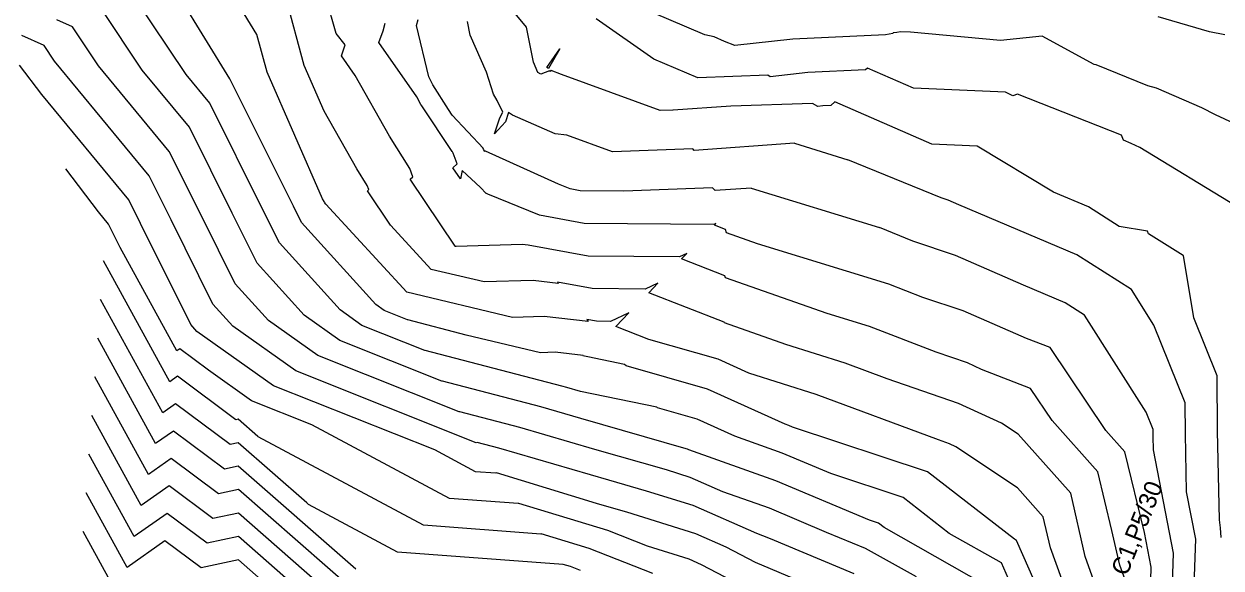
# Model space of a CAD drawing. Extents: x -549394 to -546608, y -1037055 to -1033629.
# Drawn here: x -548465 to -547751, y -1035300 to -1034976 of the extents above; entities that cross this region are included whole.
import ezdxf

# ---------------------------------------------------------------- set-up
doc = ezdxf.new("R2010")
doc.units = 0
for name, color, linetype in [('hlavni_vrst', 7, 'Continuous'), ('norm_vrst', 7, 'Continuous'), ('x_popis_velky_C1', 7, 'Continuous')]:
    doc.layers.add(name, color=color, linetype=linetype)

msp = doc.modelspace()

# ---------------------------------------------------------------- linework, layer by layer
at = {"layer": 'hlavni_vrst'}
for p, q in [((-548325.66, -1034981.81), (-548350.92, -1034940.67)), ((-548198.58, -1034982.16), (-548200.15, -1034974.14)), ((-548452.63, -1034988.35), (-548465.78, -1034982.48)), ((-548319.63, -1035004.27), (-548325.66, -1034981.81)), ((-548188.85, -1035004.3), (-548198.58, -1034982.16)), ((-548446.34, -1034997.78), (-548452.63, -1034988.35)), ((-548390, -1035066.03), (-548446.34, -1034997.78)), ((-548286.55, -1035079.75), (-548319.63, -1035004.27)), ((-548184.56, -1035017.32), (-548188.85, -1035004.3)), ((-548182.4, -1035021.26), (-548184.56, -1035017.32)), ((-548179.09, -1035028.24), (-548182.4, -1035021.26)), ((-548180.87, -1035031.46), (-548179.09, -1035028.24)), ((-548175.69, -1035028.31), (-548177.55, -1035033.94)), ((-548173.24, -1035030), (-548175.69, -1035028.31)), ((-548147.84, -1035041.1), (-548173.24, -1035030)), ((-548184.04, -1035041.05), (-548180.87, -1035031.46)), ((-548177.55, -1035033.94), (-548184.04, -1035041.05)), ((-548140.91, -1035041.86), (-548147.84, -1035041.1)), ((-548113.62, -1035051.86), (-548140.91, -1035041.86)), ((-548065.86, -1035050.08), (-548113.62, -1035051.86)), ((-548065.01, -1035050.95), (-548065.86, -1035050.08)), ((-548005.07, -1035046.73), (-548065.01, -1035050.95)), ((-548005.07, -1035046.73), (-547973.33, -1035056.54)), ((-547917.64, -1035079.24), (-547973.33, -1035056.54)), ((-548376.85, -1035092.43), (-548390, -1035066.03)), ((-548285.63, -1035081.39), (-548286.55, -1035079.75)), ((-547913.58, -1035080.58), (-547917.64, -1035079.24)), ((-547907.13, -1035083.41), (-547913.58, -1035080.58)), ((-548285.33, -1035081.86), (-548285.63, -1035081.39)), ((-548285.28, -1035081.98), (-548285.33, -1035081.86)), ((-548285.32, -1035082.01), (-548285.28, -1035081.98)), ((-548284.67, -1035082.98), (-548285.32, -1035082.01)), ((-548236.21, -1035135.54), (-548284.67, -1035082.98)), ((-547836.8, -1035113.3), (-547907.13, -1035083.41)), ((-548351.89, -1035142.66), (-548376.85, -1035092.43)), ((-547804.28, -1035133.96), (-547836.8, -1035113.3)), ((-548173.36, -1035150.54), (-548236.21, -1035135.54)), ((-547790.8, -1035155.21), (-547804.28, -1035133.96)), ((-548340.1, -1035155.69), (-548351.89, -1035142.66)), ((-548154.35, -1035149.97), (-548173.36, -1035150.54)), ((-548128.27, -1035153.07), (-548154.35, -1035149.97)), ((-548128.87, -1035151.85), (-548128.27, -1035153.07)), ((-548123.28, -1035152.88), (-548128.87, -1035151.85)), ((-548103.97, -1035147.78), (-548114.78, -1035152.95)), ((-548111.62, -1035156.06), (-548103.97, -1035147.78)), ((-548302.57, -1035182.36), (-548340.1, -1035155.69)), ((-548114.78, -1035152.95), (-548123.28, -1035152.88)), ((-548092.08, -1035163.7), (-548111.62, -1035156.06)), ((-547772.19, -1035201.51), (-547790.8, -1035155.21)), ((-548386.12, -1035225.87), (-548420.65, -1035162.96)), ((-548050.71, -1035175.57), (-548092.08, -1035163.7)), ((-548032.28, -1035183.89), (-548050.71, -1035175.57)), ((-548194.87, -1035225.3), (-548302.57, -1035182.36)), ((-547992.26, -1035196.59), (-548032.28, -1035183.89)), ((-547919.24, -1035223.68), (-547992.26, -1035196.59)), ((-547772.07, -1035219.94), (-547772.19, -1035201.51)), ((-548375.5, -1035218.38), (-548386.12, -1035225.87)), ((-548345.09, -1035241.08), (-548375.5, -1035218.38)), ((-547912.76, -1035225.91), (-547919.24, -1035223.68)), ((-547771.32, -1035254.67), (-547772.07, -1035219.94)), ((-548194.43, -1035225.12), (-548194.87, -1035225.3)), ((-548181.41, -1035228.51), (-548194.43, -1035225.12)), ((-548115.8, -1035247.72), (-548181.41, -1035228.51)), ((-547908.84, -1035227.71), (-547912.76, -1035225.91)), ((-547872.12, -1035252.29), (-547908.84, -1035227.71)), ((-548336.78, -1035239.3), (-548345.09, -1035241.08)), ((-548266.71, -1035300.68), (-548336.78, -1035239.3)), ((-548093.34, -1035254.17), (-548115.8, -1035247.72)), ((-547856.77, -1035269.47), (-547872.12, -1035252.29)), ((-548065.61, -1035262.83), (-548093.34, -1035254.17)), ((-547765.9, -1035282.86), (-547771.32, -1035254.67)), ((-548027.59, -1035279.53), (-548065.61, -1035262.83)), ((-547852.53, -1035288.02), (-547856.77, -1035269.47)), ((-548407.38, -1035318.19), (-548429.29, -1035278.27)), ((-548023.97, -1035280.82), (-548027.59, -1035279.53)), ((-548019.52, -1035282.69), (-548023.97, -1035280.82)), ((-547969.61, -1035303.43), (-548019.52, -1035282.69)), ((-547838.26, -1035327.5), (-547852.53, -1035288.02)), ((-547767.77, -1035343.03), (-547765.9, -1035282.86))]:
    msp.add_line(p, q, dxfattribs=at)
at = {"layer": 'norm_vrst'}
for p, q in [((-548278.35, -1034981.13), (-548292.99, -1034930.32)), ((-548341.75, -1035008.31), (-548379.76, -1034946.38)), ((-548164.85, -1034977.44), (-548190.85, -1034946.02)), ((-548367.9, -1035005.68), (-548401.52, -1034955.28)), ((-548297.51, -1035000.24), (-548309.57, -1034955.32)), ((-548394.04, -1035003.04), (-548418.56, -1034966.31)), ((-548058.63, -1034981.96), (-548100.16, -1034964.38)), ((-548435.59, -1034977.33), (-548445.09, -1034973.09)), ((-548230.55, -1034976.55), (-548229.52, -1034972.92)), ((-548088.99, -1034996.46), (-548123.33, -1034972.47)), ((-547757.67, -1034980.24), (-547788.2, -1034971.26)), ((-548420.19, -1035000.41), (-548435.59, -1034977.33)), ((-548272.98, -1034987.99), (-548278.35, -1034981.13)), ((-548252.94, -1034986.52), (-548250.47, -1034979.54)), ((-548250.47, -1034979.54), (-548249.2, -1034975.11)), ((-548223.12, -1035007.15), (-548230.55, -1034976.55)), ((-548160.75, -1034998.41), (-548164.85, -1034977.44)), ((-547946.54, -1034981.28), (-547946.3, -1034980.79)), ((-547944.08, -1034980.7), (-547946.3, -1034980.79)), ((-547941.91, -1034980.32), (-547944.08, -1034980.7)), ((-547935.98, -1034980.42), (-547941.91, -1034980.32)), ((-547882.24, -1034985.31), (-547935.98, -1034980.42)), ((-547748.61, -1034981.97), (-547757.67, -1034980.24)), ((-548275.29, -1034994.5), (-548272.98, -1034987.99)), ((-548230.34, -1035018.92), (-548252.94, -1034986.52)), ((-548052.96, -1034983.31), (-548058.63, -1034981.96)), ((-548046.88, -1034986.05), (-548052.96, -1034983.31)), ((-548040.77, -1034988.45), (-548046.88, -1034986.05)), ((-548006.16, -1034984.53), (-548040.77, -1034988.45)), ((-547950.83, -1034982.06), (-548006.16, -1034984.53)), ((-547946.54, -1034981.28), (-547950.83, -1034982.06)), ((-547857.36, -1034982.81), (-547882.24, -1034985.31)), ((-547857.36, -1034982.81), (-547857.36, -1034982.81)), ((-547857.36, -1034982.81), (-547857.36, -1034982.81)), ((-547826.38, -1034999.75), (-547857.36, -1034982.81)), ((-547857.36, -1034982.81), (-547857.36, -1034982.81)), ((-548267.08, -1035006.27), (-548275.29, -1034994.5)), ((-548152.72, -1035001.43), (-548144.97, -1034990.32)), ((-548144.97, -1034990.32), (-548151.83, -1035002.04)), ((-548453.9, -1035017.66), (-548467.28, -1035000.09)), ((-548377.94, -1035051.6), (-548420.19, -1035000.41)), ((-548285.5, -1035027.64), (-548297.51, -1035000.24)), ((-548158.12, -1035004.39), (-548160.75, -1034998.41)), ((-548151.83, -1035002.04), (-548152.72, -1035001.43)), ((-548062.77, -1035007.57), (-548088.99, -1034996.46)), ((-547961.61, -1035001.88), (-547962.72, -1035002.96)), ((-547934.25, -1035013.86), (-547961.61, -1035001.88)), ((-547825.25, -1034999.86), (-547826.38, -1034999.75)), ((-547794.43, -1035012.39), (-547825.25, -1034999.86)), ((-548365.87, -1035037.17), (-548394.04, -1035003.04)), ((-548353.81, -1035022.74), (-548367.9, -1035005.68)), ((-548341.75, -1035008.31), (-548341.75, -1035008.31)), ((-548303.92, -1035084.29), (-548341.75, -1035008.31)), ((-548341.75, -1035008.31), (-548341.75, -1035008.31)), ((-548341.75, -1035008.31), (-548341.75, -1035008.31)), ((-548341.75, -1035008.31), (-548341.75, -1035008.31)), ((-548246.66, -1035042.42), (-548267.08, -1035006.27)), ((-548220.78, -1035011.77), (-548223.12, -1035007.15)), ((-548156.32, -1035005.56), (-548158.12, -1035004.39)), ((-548151.28, -1035003.53), (-548156.32, -1035005.56)), ((-548150.87, -1035003.8), (-548151.28, -1035003.53)), ((-548150.53, -1035003.22), (-548150.87, -1035003.8)), ((-548150.23, -1035003.21), (-548150.53, -1035003.22)), ((-548144.1, -1035005.61), (-548150.23, -1035003.21)), ((-548085.32, -1035027.15), (-548144.1, -1035005.61)), ((-548021.12, -1035006.17), (-548062.77, -1035007.57)), ((-548019.64, -1035007.04), (-548021.12, -1035006.17)), ((-547997.16, -1035004.49), (-548019.64, -1035007.04)), ((-547962.72, -1035002.96), (-547997.16, -1035004.49)), ((-548211.54, -1035026.58), (-548220.78, -1035011.77)), ((-547879.35, -1035016.27), (-547934.25, -1035013.86)), ((-547875.02, -1035018.31), (-547879.35, -1035016.27)), ((-547789.31, -1035013.76), (-547794.43, -1035012.39)), ((-547762.3, -1035025.65), (-547789.31, -1035013.76)), ((-548402.06, -1035080.46), (-548453.9, -1035017.66)), ((-548322.15, -1035086.33), (-548353.81, -1035022.74)), ((-548228.03, -1035023.48), (-548230.34, -1035018.92)), ((-548227.43, -1035024.45), (-548228.03, -1035023.48)), ((-547994.44, -1035022.94), (-548043.03, -1035024.57)), ((-547991.25, -1035024.81), (-547994.44, -1035022.94)), ((-547981.06, -1035021.97), (-547983.4, -1035024.24)), ((-547923.31, -1035047.26), (-547981.06, -1035021.97)), ((-547872.2, -1035017.4), (-547875.02, -1035018.31)), ((-547810.24, -1035041.96), (-547872.2, -1035017.4)), ((-548266.14, -1035061.9), (-548285.5, -1035027.64)), ((-548209.24, -1035051.53), (-548227.43, -1035024.45)), ((-548209.31, -1035029.91), (-548211.54, -1035026.58)), ((-548190.65, -1035049.83), (-548209.31, -1035029.91)), ((-548077.69, -1035026.86), (-548085.32, -1035027.15)), ((-548077.56, -1035027), (-548077.69, -1035026.86)), ((-548043.03, -1035024.57), (-548077.56, -1035027)), ((-547988.15, -1035024.46), (-547991.25, -1035024.81)), ((-547983.4, -1035024.24), (-547988.15, -1035024.46)), ((-547754.19, -1035029.66), (-547762.3, -1035025.65)), ((-547730.63, -1035040.65), (-547754.19, -1035029.66)), ((-548340.39, -1035088.36), (-548365.87, -1035037.17)), ((-548234.43, -1035061.72), (-548246.66, -1035042.42)), ((-547809.05, -1035044.85), (-547810.24, -1035041.96)), ((-547804.46, -1035046.79), (-547809.05, -1035044.85)), ((-548358.62, -1035090.4), (-548377.94, -1035051.6)), ((-548209.06, -1035051.73), (-548209.24, -1035051.53)), ((-548208.83, -1035052.15), (-548209.06, -1035051.73)), ((-548209.06, -1035051.73), (-548209.06, -1035051.73)), ((-548208.64, -1035052.6), (-548208.83, -1035052.15)), ((-548190.85, -1035049.89), (-548190.65, -1035049.83)), ((-548190.6, -1035050.34), (-548190.85, -1035049.89)), ((-548190.33, -1035050.52), (-548190.6, -1035050.34)), ((-548189.76, -1035051.65), (-548190.33, -1035050.52)), ((-548189.69, -1035051.4), (-548189.76, -1035051.65)), ((-548189.33, -1035051.47), (-548189.69, -1035051.4)), ((-548145.92, -1035071.14), (-548189.33, -1035051.47)), ((-547896.2, -1035048.45), (-547923.31, -1035047.26)), ((-547850.71, -1035075.86), (-547896.2, -1035048.45)), ((-547799.24, -1035049.25), (-547804.46, -1035046.79)), ((-547741.82, -1035084.17), (-547799.24, -1035049.25)), ((-548208.8, -1035061.28), (-548206.31, -1035059.06)), ((-548206.31, -1035059.06), (-548208.64, -1035052.6)), ((-548420.09, -1035087.67), (-548439.72, -1035061.88)), ((-548259.88, -1035071.79), (-548266.14, -1035061.9)), ((-548232.64, -1035066.7), (-548234.43, -1035061.72)), ((-548234.31, -1035068.19), (-548232.64, -1035066.7)), ((-548204.27, -1035068), (-548208.8, -1035061.28)), ((-548203.26, -1035063.01), (-548204.27, -1035068)), ((-548192.4, -1035072.99), (-548203.26, -1035063.01)), ((-548258.96, -1035074.34), (-548259.88, -1035071.79)), ((-548207.48, -1035107.98), (-548234.31, -1035068.19)), ((-548189.04, -1035076.69), (-548192.4, -1035072.99)), ((-548138.99, -1035073.95), (-548145.92, -1035071.14)), ((-548054.02, -1035073.3), (-548107, -1035075.28)), ((-548052.47, -1035074.91), (-548054.02, -1035073.3)), ((-548030.95, -1035073.39), (-548052.47, -1035074.91)), ((-548030.95, -1035073.39), (-547954.5, -1035097.01)), ((-548395.09, -1035094.47), (-548402.06, -1035080.46)), ((-548259.82, -1035075.1), (-548258.96, -1035074.34)), ((-548246.07, -1035095.48), (-548259.82, -1035075.1)), ((-548188.86, -1035076.72), (-548189.04, -1035076.69)), ((-548188.01, -1035077.11), (-548188.86, -1035076.72)), ((-548157.19, -1035089.62), (-548188.01, -1035077.11)), ((-548133, -1035075.05), (-548138.99, -1035073.95)), ((-548107, -1035075.28), (-548133, -1035075.05)), ((-547829.89, -1035084.71), (-547850.71, -1035075.86)), ((-548414.12, -1035094.89), (-548420.09, -1035087.67)), ((-548312.32, -1035106.11), (-548322.15, -1035086.33)), ((-548299.13, -1035093.93), (-548303.92, -1035084.29)), ((-547811.64, -1035096.31), (-547829.89, -1035084.71)), ((-548413.32, -1035096.51), (-548414.12, -1035094.89)), ((-548365.08, -1035154.84), (-548395.09, -1035094.47)), ((-548338.7, -1035130.48), (-548358.62, -1035090.4)), ((-548325.51, -1035118.29), (-548340.39, -1035088.36)), ((-548254.8, -1035142.92), (-548299.13, -1035093.93)), ((-548130.57, -1035094.51), (-548157.19, -1035089.62)), ((-548053.19, -1035095.18), (-548130.57, -1035094.51)), ((-548052.09, -1035094.65), (-548053.19, -1035095.18)), ((-548052.87, -1035095.49), (-548052.09, -1035094.65)), ((-548407.15, -1035108.92), (-548413.32, -1035096.51)), ((-548221.72, -1035121.89), (-548246.07, -1035095.48)), ((-548046.33, -1035098.05), (-548052.87, -1035095.49)), ((-548045.7, -1035100.13), (-548046.33, -1035098.05)), ((-548027.19, -1035106.63), (-548045.7, -1035100.13)), ((-547934.51, -1035105.16), (-547954.5, -1035097.01)), ((-547794.56, -1035099.15), (-547811.64, -1035096.31)), ((-547794.13, -1035100.78), (-547794.56, -1035099.15)), ((-547773.33, -1035113.67), (-547794.13, -1035100.78)), ((-548373.36, -1035170.48), (-548407.15, -1035108.92)), ((-548276.12, -1035146.11), (-548312.32, -1035106.11)), ((-548207.23, -1035108.24), (-548207.48, -1035107.98)), ((-548206.92, -1035108.31), (-548207.23, -1035108.24)), ((-548167.47, -1035107.13), (-548206.92, -1035108.31)), ((-548163.87, -1035107.56), (-548167.47, -1035107.13)), ((-548163.96, -1035107.39), (-548163.87, -1035107.56)), ((-548128.14, -1035113.97), (-548163.96, -1035107.39)), ((-547948.96, -1035130.8), (-548027.19, -1035106.63)), ((-547909.04, -1035113.59), (-547934.51, -1035105.16)), ((-548073.72, -1035114.44), (-548128.14, -1035113.97)), ((-548069.38, -1035112.36), (-548073.72, -1035114.44)), ((-548072.45, -1035115.68), (-548069.38, -1035112.36)), ((-548046.67, -1035125.76), (-548072.45, -1035115.68)), ((-547868.67, -1035131.29), (-547909.04, -1035113.59)), ((-547773.1, -1035113.71), (-547773.33, -1035113.67)), ((-547767.07, -1035150.78), (-547773.1, -1035113.71)), ((-548377.61, -1035188.94), (-548417.19, -1035116.83)), ((-548297.45, -1035149.3), (-548325.51, -1035118.29)), ((-548190.14, -1035129.42), (-548221.72, -1035121.89)), ((-548318.77, -1035152.5), (-548338.7, -1035130.48)), ((-548160.91, -1035128.55), (-548190.14, -1035129.42)), ((-548146.07, -1035130.32), (-548160.91, -1035128.55)), ((-548146.41, -1035129.62), (-548146.07, -1035130.32)), ((-548125.71, -1035133.42), (-548146.41, -1035129.62)), ((-548086.67, -1035130.07), (-548094.25, -1035133.7)), ((-548092.03, -1035135.87), (-548086.67, -1035130.07)), ((-548046.3, -1035126.98), (-548046.67, -1035125.76)), ((-547985.72, -1035148.24), (-548046.3, -1035126.98)), ((-547928.56, -1035138.64), (-547948.96, -1035130.8)), ((-548094.25, -1035133.7), (-548125.71, -1035133.42)), ((-548047.01, -1035153.47), (-548092.03, -1035135.87)), ((-547843.71, -1035141.89), (-547868.67, -1035131.29)), ((-548381.87, -1035207.4), (-548418.92, -1035139.9)), ((-548249.9, -1035146.4), (-548254.8, -1035142.92)), ((-547904.5, -1035146.6), (-547928.56, -1035138.64)), ((-547832.17, -1035149.23), (-547843.71, -1035141.89)), ((-548276.24, -1035164.38), (-548297.45, -1035149.3)), ((-548263.07, -1035155.39), (-548276.12, -1035146.11)), ((-548235.85, -1035152), (-548249.9, -1035146.4)), ((-548235.8, -1035151.97), (-548235.85, -1035152)), ((-548200.97, -1035161.06), (-548235.8, -1035151.97)), ((-547960.35, -1035156.08), (-547985.72, -1035148.24)), ((-547866.89, -1035163.09), (-547904.5, -1035146.6)), ((-547795.44, -1035207.12), (-547832.17, -1035149.23)), ((-547753.12, -1035185.49), (-547767.07, -1035150.78)), ((-548361.42, -1035158.88), (-548365.08, -1035154.84)), ((-548315.74, -1035191.35), (-548361.42, -1035158.88)), ((-548289.41, -1035173.37), (-548318.77, -1035152.5)), ((-548225.61, -1035170.32), (-548263.07, -1035155.39)), ((-548046.9, -1035153.83), (-548047.01, -1035153.47)), ((-548010.34, -1035166.66), (-548046.9, -1035153.83)), ((-547920.67, -1035171.32), (-547960.35, -1035156.08)), ((-548215.36, -1035188.65), (-548276.24, -1035164.38)), ((-548156.58, -1035171.65), (-548200.97, -1035161.06)), ((-547974.87, -1035177.92), (-548010.34, -1035166.66)), ((-547852.74, -1035168.6), (-547866.89, -1035163.09)), ((-548371.71, -1035169.32), (-548373.36, -1035170.48)), ((-548354.66, -1035182.04), (-548371.71, -1035169.32)), ((-548205.12, -1035206.97), (-548289.41, -1035173.37)), ((-548225.46, -1035170.26), (-548225.61, -1035170.32)), ((-548143.9, -1035191.54), (-548225.46, -1035170.26)), ((-548147.79, -1035171.39), (-548156.58, -1035171.65)), ((-548131.22, -1035173.36), (-548147.79, -1035171.39)), ((-548131.29, -1035173.48), (-548131.22, -1035173.36)), ((-548128.29, -1035174.13), (-548131.29, -1035173.48)), ((-547902.04, -1035177.74), (-547920.67, -1035171.32)), ((-547819.51, -1035217.98), (-547852.74, -1035168.6)), ((-548106.43, -1035178.62), (-548128.29, -1035174.13)), ((-548105.55, -1035179.49), (-548106.43, -1035178.62)), ((-548056.94, -1035193.44), (-548105.55, -1035179.49)), ((-547949.88, -1035187.19), (-547974.87, -1035177.92)), ((-547893.61, -1035181.6), (-547902.04, -1035177.74)), ((-548390.37, -1035244.33), (-548422.38, -1035186.02)), ((-548372.98, -1035185.67), (-548377.61, -1035188.94)), ((-548338.19, -1035211.63), (-548372.98, -1035185.67)), ((-548328.91, -1035200.35), (-548354.66, -1035182.04)), ((-547907.4, -1035201.83), (-547949.88, -1035187.19)), ((-547864.35, -1035193), (-547893.61, -1035181.6)), ((-547752.91, -1035218.21), (-547753.12, -1035185.49)), ((-548219.68, -1035229.65), (-548315.74, -1035191.35)), ((-548215.11, -1035188.54), (-548215.36, -1035188.65)), ((-548156.4, -1035203.86), (-548215.11, -1035188.54)), ((-548140.97, -1035192.39), (-548143.9, -1035191.54)), ((-548132.76, -1035194.75), (-548140.97, -1035192.39)), ((-548087.27, -1035204.09), (-548132.76, -1035194.75)), ((-548010.67, -1035214.34), (-548056.94, -1035193.44)), ((-547851.51, -1035212.09), (-547864.35, -1035193)), ((-548374.24, -1035202.03), (-548381.87, -1035207.4)), ((-548341.64, -1035226.35), (-548374.24, -1035202.03)), ((-548292.89, -1035214.71), (-548328.91, -1035200.35)), ((-547881.71, -1035213.59), (-547907.4, -1035201.83)), ((-548394.62, -1035262.8), (-548424.11, -1035209.09)), ((-548204.77, -1035206.83), (-548205.12, -1035206.97)), ((-548168.91, -1035216.19), (-548204.77, -1035206.83)), ((-548132.58, -1035210.83), (-548156.4, -1035203.86)), ((-548086.85, -1035204.51), (-548087.27, -1035204.09)), ((-548063.16, -1035211.31), (-548086.85, -1035204.51)), ((-547791.26, -1035217.52), (-547795.44, -1035207.12)), ((-548336.8, -1035211.33), (-548338.19, -1035211.63)), ((-548325.13, -1035221.56), (-548336.8, -1035211.33)), ((-548210.93, -1035258.6), (-548292.89, -1035214.71)), ((-548124.19, -1035229.28), (-548168.91, -1035216.19)), ((-548069.67, -1035228.92), (-548132.58, -1035210.83)), ((-548040.62, -1035221.49), (-548063.16, -1035211.31)), ((-548008.58, -1035215.08), (-548010.67, -1035214.34)), ((-548006.43, -1035215.99), (-548008.58, -1035215.08)), ((-547925.74, -1035242.76), (-548006.43, -1035215.99)), ((-547871.79, -1035220.23), (-547881.71, -1035213.59)), ((-547824.3, -1035242.74), (-547851.51, -1035212.09)), ((-548324.86, -1035221.85), (-548325.13, -1035221.56)), ((-548226.43, -1035274.57), (-548324.86, -1035221.85)), ((-548012.43, -1035231.52), (-548040.62, -1035221.49)), ((-547840.45, -1035255.3), (-547871.79, -1035220.23)), ((-547808.21, -1035230.71), (-547819.51, -1035217.98)), ((-547791.23, -1035221.67), (-547791.26, -1035217.52)), ((-547791.06, -1035229.48), (-547791.23, -1035221.67)), ((-547751.76, -1035271.29), (-547752.91, -1035218.21)), ((-548336.79, -1035225.31), (-548341.64, -1035226.35)), ((-548295.92, -1035261.12), (-548336.79, -1035225.31)), ((-548195.44, -1035242.64), (-548219.68, -1035229.65)), ((-548081.51, -1035241.55), (-548124.19, -1035229.28)), ((-548069, -1035229.13), (-548069.67, -1035228.92)), ((-548068.07, -1035229.54), (-548069, -1035229.13)), ((-548016.28, -1035247.95), (-548068.07, -1035229.54)), ((-547796.48, -1035278.86), (-547808.21, -1035230.71)), ((-547779.2, -1035291.22), (-547791.06, -1035229.48)), ((-548398.88, -1035281.26), (-548425.84, -1035232.15)), ((-548376.76, -1035234.74), (-548390.37, -1035244.33)), ((-548348.53, -1035255.8), (-548376.76, -1035234.74)), ((-547983.38, -1035243.75), (-548012.43, -1035231.52)), ((-548183.29, -1035243.54), (-548195.44, -1035242.64)), ((-548182.83, -1035243.35), (-548183.29, -1035243.54)), ((-548123.2, -1035261.54), (-548182.83, -1035243.35)), ((-548067.3, -1035245.98), (-548081.51, -1035241.55)), ((-547940.39, -1035258.01), (-547983.38, -1035243.75)), ((-547873.98, -1035282.93), (-547925.74, -1035242.76)), ((-547815.82, -1035277.57), (-547824.3, -1035242.74)), ((-548378.02, -1035251.1), (-548394.62, -1035262.8)), ((-548351.98, -1035270.53), (-548378.02, -1035251.1)), ((-548047.83, -1035254.54), (-548067.3, -1035245.98)), ((-547960.33, -1035271.5), (-548016.28, -1035247.95)), ((-548403.13, -1035299.73), (-548427.57, -1035255.21)), ((-548336.76, -1035253.28), (-548348.53, -1035255.8)), ((-548265.98, -1035315.28), (-548336.76, -1035253.28)), ((-548169.87, -1035261.65), (-548210.93, -1035258.6)), ((-548020.12, -1035264.38), (-548047.83, -1035254.54)), ((-547912.82, -1035279.41), (-547940.39, -1035258.01)), ((-547831.8, -1035293.19), (-547840.45, -1035255.3)), ((-548295, -1035262.11), (-548295.92, -1035261.12)), ((-548241.92, -1035290.54), (-548295, -1035262.11)), ((-548169.55, -1035261.53), (-548169.87, -1035261.65)), ((-548116.37, -1035277.74), (-548169.55, -1035261.53)), ((-548107.4, -1035266.16), (-548123.2, -1035261.54)), ((-548105.18, -1035266.8), (-548107.4, -1035266.16)), ((-547985.96, -1035278.77), (-548020.12, -1035264.38)), ((-548379.28, -1035267.45), (-548398.88, -1035281.26)), ((-548355.43, -1035285.25), (-548379.28, -1035267.45)), ((-548336.75, -1035267.26), (-548351.98, -1035270.53)), ((-548273.28, -1035322.85), (-548336.75, -1035267.26)), ((-548063.91, -1035279.67), (-548105.18, -1035266.8)), ((-547955.05, -1035273.26), (-547960.33, -1035271.5)), ((-547951.66, -1035275.88), (-547955.05, -1035273.26)), ((-547751.1, -1035276.17), (-547751.76, -1035271.29)), ((-548156.45, -1035279.77), (-548226.43, -1035274.57)), ((-548156.28, -1035279.7), (-548156.45, -1035279.77)), ((-548127.49, -1035288.48), (-548156.28, -1035279.7)), ((-548092.73, -1035286.95), (-548116.37, -1035277.74)), ((-548045.93, -1035287.57), (-548063.91, -1035279.67)), ((-547962.88, -1035288.36), (-547985.96, -1035278.77)), ((-547890.77, -1035310.38), (-547951.66, -1035275.88)), ((-547881.78, -1035296.99), (-547912.82, -1035279.41)), ((-547811.08, -1035298.35), (-547815.82, -1035277.57)), ((-547792.5, -1035299.58), (-547796.48, -1035278.86)), ((-547750.74, -1035281.82), (-547751.1, -1035276.17)), ((-548380.55, -1035283.81), (-548403.13, -1035299.73)), ((-548358.88, -1035299.98), (-548380.55, -1035283.81)), ((-548336.73, -1035281.24), (-548355.43, -1035285.25)), ((-548280.59, -1035330.42), (-548336.73, -1035281.24)), ((-548068.01, -1035294.69), (-548092.73, -1035286.95)), ((-548028.33, -1035296.81), (-548045.93, -1035287.57)), ((-547872.79, -1035283.61), (-547873.98, -1035282.93)), ((-547848.15, -1035338.86), (-547872.79, -1035283.61)), ((-548336.72, -1035295.22), (-548358.88, -1035299.98)), ((-548287.89, -1035337.99), (-548336.72, -1035295.22)), ((-548143.03, -1035297.88), (-548241.92, -1035290.54)), ((-548089.6, -1035303.24), (-548127.49, -1035288.48)), ((-548060.62, -1035298.12), (-548068.01, -1035294.69)), ((-547932.49, -1035305.23), (-547962.88, -1035288.36)), ((-547818.99, -1035328.63), (-547831.8, -1035293.19)), ((-547780.25, -1035325.12), (-547779.2, -1035291.22)), ((-548143, -1035297.87), (-548143.03, -1035297.88)), ((-548138.61, -1035299.21), (-548143, -1035297.87)), ((-548132.83, -1035301.46), (-548138.61, -1035299.21)), ((-548032.78, -1035312.73), (-548060.62, -1035298.12)), ((-548005.35, -1035306.45), (-548028.33, -1035296.81)), ((-547863.51, -1035337.97), (-547881.78, -1035296.99)), ((-547805.76, -1035313.06), (-547811.08, -1035298.35)), ((-547792.74, -1035307.2), (-547792.5, -1035299.58))]:
    msp.add_line(p, q, dxfattribs=at)

# ---------------------------------------------------------------- texts
at = {"layer": 'x_popis_velky_C1'}
msp.add_text('C1,P5/30', height=10.5, rotation=68.23499, dxfattribs=at).set_placement((-547806.96, -1035305.34))

doc.saveas('drawing.dxf')
